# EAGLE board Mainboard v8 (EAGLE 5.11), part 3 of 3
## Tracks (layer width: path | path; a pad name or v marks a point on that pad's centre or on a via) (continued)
USART1-TX  (via drill 0.3)
  Top 0.254: IC16.101 67,76.21 v67.79,77 | v75.72,79.22 75.72,78.58 76.68,77.63 79.22,77.63 82.39,80.81 99.22,80.81 105.25,86.84 111.92,86.84 115.06,89.97 IC15.5
  Bottom 0.254: v67.79,77 70.33,79.53 75.41,79.53 v75.72,79.22
V+  (via drill 0.81)
  Top 0.254: IC22.3 61.75,10 61.12,10 60.17,10.95 59.53,10.95 | IC20.3 61.75,18.26 61.12,18.26 60.17,19.21 59.53,19.21 | IC17.3 61.75,26.51 61.12,26.51 59.85,27.78 59.27,27.78 R69.1
  other vias: 59.22,17.62 59.22,9.37 56.36,26.83 56.36,25.56 55.09,26.83 55.09,25.56
  pour Bottom (no thermals): 34.45,18.89 36.67,16.67 53.5,16.67 57.31,12.86 57.31,9.68 58.58,8.41 59.85,8.41 59.85,17.94 57.94,19.84 54.14,19.84 53.18,20.8 34.45,20.8
  pour Top (no thermals): 57.94,20.16 57.94,17.94 58.9,16.99 59.53,16.99 60.48,17.94 60.48,20.16
  pour Top (no thermals): 57.94,11.91 57.94,9.68 58.9,8.73 59.53,8.73 60.48,9.68 60.48,11.91
  pour Bottom (no thermals): 38.58,24.92 52.55,24.92 55.09,27.47 56.99,27.47 56.99,24.92 53.18,20.8 34.45,20.8 34.45,21.11 38.26,24.92
  pour Top (no thermals): 60.64,28.58 56.2,28.58 54.45,26.83 54.45,25.56 55.09,24.92 56.99,24.92 56.99,26.51 57.31,26.83 60.64,26.83
VCC  (via drill 0.3, 0.81)
  Top 0.254: IC17.4 61.75,23.34 61.75,23.02 60.8,22.07 59.27,22.07 R69.2 | IC1.1 86.94,75.72 FLT1.A
  Top 0.406: v94.78,22.7 94.78,23.88 FLT4.A | IC3.1 34.13,28.1 | v90.01,45.88 IC4.1 | IC28.4 17.88,86.2 R30.2 | FLT5.A 26.83,86.36 v26.83,87.47 | IC6.4 17.88,56.99 R12.2 | IC7.4 19.53,48.74 C18.A | IC26.4 100.49,55.09 C2.A | IC27.4 102.14,48.1 R24.2 | FLT3.A 26.29,25.66 27.94,27.31 28.73,28.1 v30.01,28.1 | FLT2.A 33.28,77.73 v33.18,77.63
  Top 0.61: v90.01,75.72 IC1.1 | v30.01,28.1 IC3.1 | v30.01,59.22 IC2.1 31.91,59.22 | v30.01,88.42 IC5.1
  Bottom 0.406: 91.42,28.26 D15.A | 91.44,28.26 93.35,28.26 94.78,26.83 v94.78,22.7 | D13.A v90.01,45.88 | v33.18,77.63 28.73,73.19 28.73,69.51 D7.A | v26.83,87.47 26.83,86.52 27.15,86.2 27.15,85.89
  Bottom 0.61: C34.B 23.02,83.34 24.61,83.34 27.15,85.89 28.73,87.47 28.73,88.42 | EXTPWR.3 v78.9,22.38 v79.85,22.38 | 91.28,65.56 91.28,58.9 96.05,54.14 C2.A | 91.28,65.56 D3.A | 91.28,65.56 91.28,70.64 | 91.28,70.64 D2.A | 91.28,70.64 91.28,75.72 | 91.28,75.72 v90.01,75.72 | 91.28,75.72 D1.A | 91.6,45.88 D13.A | 91.6,40.8 91.6,45.88 | 91.6,40.8 D14.A | 91.6,40.8 91.6,35.72 D15.A | 28.73,38.26 28.73,44.93 27.78,45.88 24.29,49.37 23.97,49.69 C18.A | 28.73,38.26 D11.A | 28.73,33.18 28.73,38.26 | 28.73,33.18 D10.A | 28.73,33.18 28.73,28.1 D9.A v30.01,28.1 | 28.73,59.22 28.73,58.26 28.1,58.26 23.97,54.14 C10.A | 28.73,59.22 28.73,64.3 | 28.73,64.3 28.73,69.38 D7.A | 28.73,64.3 D6.A | 28.73,59.22 D5.A | 28.73,59.22 v30.01,59.22 | 28.73,88.42 28.73,93.5 | 28.73,93.5 28.73,98.58 D19.A | 28.73,93.5 D18.A | 28.73,88.42 D17.A | 28.73,88.42 v30.01,88.42 | 91.6,45.88 91.6,46.52 95.09,50.01 96.05,50.96 C26.B
  other vias: 59.85,23.97 58.58,23.97 58.58,25.24 59.85,25.24
  pour Supply (no thermals): 9.68,108.11 19.84,108.11 19.84,24.92 24.92,19.84 48.42,19.84 54.77,26.2 57.94,26.2 57.94,21.75 47.78,11.59 36.35,11.59 26.2,1.43 16.04,1.43 16.04,17.3 9.68,23.66
  pour Supply (no thermals): 100.49,60.48 100.49,27.47 96.68,23.66 64.3,23.66 61.75,26.2 57.94,26.2 57.94,21.75 55.41,19.21 103.03,19.21 110.65,26.83 110.65,60.48
  pour Top (no thermals): 57.94,21.43 57.94,25.56 58.26,25.88 60.17,25.88 60.48,25.56 60.48,21.43
  pour Top (no thermals): 104.3,53.18 101.44,53.18 100.81,53.82 100.81,54.45 101.76,55.41 101.76,57.94 103.03,57.94 103.03,56.04 104.3,54.77
  pour Top (no thermals): 104.3,51.91 101.44,51.91 100.81,51.28 100.81,50.64 101.76,49.69 101.76,47.15 103.03,47.15 103.03,49.05 104.3,50.33
  pour Top (no thermals): 15.72,50.64 18.57,50.64 19.21,50.01 19.21,49.37 18.26,48.42 18.26,45.88 16.99,45.88 16.99,47.78 15.72,49.05
  pour Top (no thermals): 15.72,53.18 18.57,53.18 19.21,53.82 19.21,54.45 18.26,55.41 18.26,57.94 16.99,57.94 16.99,56.04 15.72,54.77
  pour Top (no thermals): 15.72,82.39 18.57,82.39 19.21,83.03 19.21,83.66 18.26,84.61 18.26,87.16 16.99,87.16 16.99,85.25 15.72,83.98
VCC-A
  Top 0.254: IC25.22 92.31,15.01 91.6,15.72 88.9,15.72 87.63,16.99 86.04,16.99 85.53,16.47 CN12.1 RN22.8
VCC-SHUNT
  Top 0.254: IC17.1 | IC17.1 R72.2 | IC17.1 63.66,25.88 66.52,23.02 68.74,23.02 69.62,22.14 RN23.6
VCCUSB  (via drill 0.3)
  Top 0.254: IC15.19 IC15.20 109.04,92.58 v108.75,92.87 108.75,96.36 R57.2 C61.1 109.38,100.81 v108.9,100.81
  Bottom 0.254: USB1.1 107.47,104.66 107.47,102.24 v108.9,100.81
VOP1
  Top 0.254: IC9.5 C47.1 R47.2
WF-CE
  Top 0.254: IC16.37 50.78,92.09 47.78,95.09 47.78,101.12 42.55,106.36 37.47,106.36 WF1.3
WF-CS  (via drill 0.3)
  Top 0.254: IC16.46 52.67,87.59 53.5,88.42 v53.5,91.6 | v47.31,94.14 47.31,100.97 42.39,105.89 36.51,105.89 34.61,107.79 34.61,109.54 WF1.4
  Bottom 0.254: v53.5,91.6 51.28,91.6 48.74,94.14 v47.31,94.14
WF-IRQ  (via drill 0.3)
  Top 0.254: IC16.63 53.38,79.09 55.41,81.12 55.41,90.97 v54.45,91.92 | v45.4,94.78 45.4,100.97 41.91,104.46 36.04,104.46 33.81,106.68 30.64,106.68 29.69,107.63 29.69,109.7 WF1.8
  Bottom 0.254: v54.45,91.92 52.55,93.82 51.91,93.82 50.96,94.78 v45.4,94.78

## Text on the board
tPlace: - | + | - | + | + | -
tNames: Mainboard v8 | Design: A.Ryll | Tigers Mannheim | BAT B | BAT A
